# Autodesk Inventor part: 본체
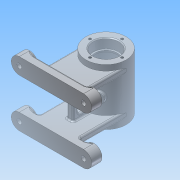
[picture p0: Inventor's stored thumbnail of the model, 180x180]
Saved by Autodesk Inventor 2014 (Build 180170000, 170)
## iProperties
Created: 2015-11
Part Number: 본체
Material: 알루미늄 6061
Document SubType Name: Modeling
Designer: net
Density: 2.71 g/cm^3
Appearance: 알루미늄 - 평지
Mass: 357.463 g
Surface Area: 461.435 cm^2
Volume: 131.905 cm^3
Author: net
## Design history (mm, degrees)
sketch "스케치1"
  geometry: C1 r 25 at (0, 0); 1 further point
  constraints: 1 centre point, 1 coincident
  dimensions: "d0" = 50 diameter of C1
extrude "돌출1" new body sketch "스케치1" stored distance "d1" = 70; taper "d2" = 0 deg
node "작업 평면1"
sketch "스케치2"
  geometry: L1 (-25, -35)-(25, -35) reference; L2 (25, 35)-(-25, 35) reference; L3 (40, -20)-(-40, -20); L4 (-40, -20)-(-40, -40); L5 (-40, -40)-(40, -40); L6 (40, -40)-(40, -20); L7 (40, 40)-(-40, 40); L8 (-40, 40)-(-40, 20); L9 (-40, 20)-(40, 20); L10 (40, 20)-(40, 40); 7 further points
  constraints: 16 end point, 6 midpoint, 6 vertical alignment, 4 parallel, 2 horizontal, 2 perpendicular, 8 other
  dimensions: "d4" = 40 distance from line of L5 point (0, 0); "d5" = 80 distance between parallel lines of L7 L5; "d6" = 20 distance of L7.end L8.end; "d7" = 20 distance of L3.end L4.end; "d8" = 80 distance of L4.end L5.end; "d9" = 80 distance of L7.start L7.end
  node "투영된 루프1"
extrude "돌출2" join sketch "스케치2" distance "d10" = 10; taper "d11" = 0 deg
extrude "돌출3" join sketch "스케치2" distance "d12" = 13; taper "d13" = 0 deg
node "작업 평면2"
sketch "스케치3"
  geometry: L1 (40, 40)-(-40, 40) reference; L2 (-40, 20)-(40, 20) reference; L3 (-40, -40)-(40, -40) reference; L4 (40, -20)-(-40, -20) reference; L5 (-25, 28)-(25, 28); L6 (25, 28)-(25, 20); L7 (25, 20)-(-25, 20); L8 (-25, 20)-(-25, 28); L9 (-25, -20)-(25, -20); L10 (25, -20)-(25, -28); L11 (25, -28)-(-25, -28); L12 (-25, -28)-(-25, -20); A1 r 10 centre (40, 30) between (40, 40) and (40, 20) reference; A2 r 10 centre (-40, 30) between (-40, 20) and (-40, 40) reference; A3 r 10 centre (-40, -30) between (-40, -40) and (-40, -20) reference; A4 r 10 centre (40, -30) between (40, -20) and (40, -40) reference; 5 further points
  constraints: 16 end point, 4 coincident, 4 midpoint, 4 parallel, 2 horizontal, 2 perpendicular
  dimensions: "d15" = 50 distance of L5.start L5.end; "d16" = 50 distance of L10.end L11.end; "d17" = 8 distance of L9.end L10.end; "d18" = 8 distance of L5.end L6.end
extrude "돌출4" join sketch "스케치3" stored distance "d19" = 13; taper "d20" = 0 deg
node "작업 평면3"
sketch "스케치4"
  geometry: L1 (-40, 20)-(40, 20) reference; L2 (40, -20)-(-40, -20) reference; L3 (4, 20)-(-4, 20); L4 (-4, 20)-(-4, -20); L5 (-4, -20)-(4, -20); L6 (4, -20)-(4, 20); 2 further points
  constraints: 8 end point, 2 parallel, 2 point on line, 1 horizontal, 1 midpoint, 1 perpendicular, 1 vertical alignment
  dimensions: "d22" = 8 distance between parallel lines of L4 L6
extrude "돌출5" join sketch "스케치4" stored distance "d23" = 13; taper "d24" = 0 deg
sketch "스케치5"
  geometry: L1 (-68, 40)-(-68, 20) reference; L2 (-24.678, 20)-(-24.678, -20) reference; L3 (-45, 20)-(-24.678, 20) reference; L4 (-45, 20)-(-45, -20) reference; L5 (-24.678, -20)-(-45, -20) reference; L6 (-31.5, 11.5)-(-31.5, -11.5); L7 (-38.5, 11.5)-(-38.5, -11.5); A1 r 3.5 centre (-35, 11.5) between (-31.5, 11.5) and (-38.5, 11.5); A2 r 3.5 centre (-35, -11.5) between (-38.5, -11.5) and (-31.5, -11.5); 2 further points
  constraints: 4 end point, 4 point on circle, 3 tangent, 2 centre point, 1 horizontal alignment, 1 midpoint, 1 parallel, 1 perpendicular
  dimensions: "d25" = 33 distance from line of A1.centre L1; "d26" = 7 diameter of A2; "d27" = 7 diameter of A1; "d28" = 23 distance of L7.start L7.end
extrude "돌출6" cut sketch "스케치5" stored distance "d29" = 13; taper "d30" = 0 deg
sketch "스케치6"
  geometry: L1 (25, 35)-(-25, 35) reference; L2 (25, -35)-(25, 35) reference; L3 (-25, -35)-(25, -35) reference; L4 (0, 62.563)-(0, -62.563); L5 (16, -35)-(16, -23); L6 (16, -23)-(14, -23); L7 (14, -23)-(14, -21); L8 (14, -21)-(21, -21); L9 (21, -21)-(21, 21); L10 (21, 21)-(14, 21); L11 (14, 21)-(14, 23); L12 (14, 23)-(16, 23); L13 (16, 23)-(16, 35); L14 (0, 35)-(16, 35); L15 (0, -35)-(16, -35); L16 (0, -35)-(0, 35); 3 further points
  constraints: 26 end point, 7 parallel, 4 midpoint, 4 point on line, 3 collinear, 3 perpendicular, 2 coincident, 1 horizontal alignment
  dimensions: "d31" = 32 diameter of L5 L4; "d32" = 28 diameter of L7 L4; "d33" = 32 diameter of L13 L4; "d34" = 28 diameter of L11 L4; "d35" = 42 diameter of L9 L4; "d36" = 12 distance of L5.start L5.end; "d37" = 12 distance of L12.end L13.end; "d38" = 42 distance of L8.end L9.end
revolve "회전1" sketch "스케치6" stored, may be unused: angle "d39" = 90 deg
node "작업 평면4"
sketch "스케치7"
  geometry: L1 (25, 35)-(-25, 35) reference; L2 (-25, -35)-(25, -35) reference; C1 r 5 at (0, 0); 1 further point
  constraints: 1 centre point, 1 coincident
  dimensions: "d41" = 10 diameter of C1
extrude "돌출7" join sketch "스케치7" stored distance "d42" = 13; taper "d43" = 0 deg
sketch "스케치8"
  geometry: L1 (0, 0)-(9.424, 0); L2 (0, 0)-(14, -24.249); L3 (0, 0)-(0, -8.439); C1 r 25 at (0, 0) reference; 1 further point
  constraints: 6 end point, 1 horizontal, 1 perpendicular
  dimensions: "d44" = 30 deg angle of L2 L3; "d45" = 28 distance of L1.start L2.end
node "작업 평면5"
sketch "스케치9"
  geometry: C1 r 6 at (0, 0); 1 further point
  constraints: 1 centre point, 1 coincident
  dimensions: "d46" = 12 diameter of C1
extrude "돌출8" join sketch "스케치9" stored distance "d47" = 13; taper "d48" = 0 deg
node "작업 평면6"
sketch "스케치10"
  geometry: 2 further points
  constraints: 2 coincident, 1 other
feature "엠보싱1" sketch "스케치10" dims "d4" = 40, "d5" = 80, "d6" = 20, "d7" = 20, "d8" = 80, "d9" = 80, "d49" = 0.5, "d50" = 0
fillet "모깎기1" dims "d51" = 0.3
chamfer "모따기1" distance "d52" = 1; stored, may be unused: second distance "d53" = 2, angle "d54" = 45 deg
fillet "모깎기2" dims "d55" = 3
fillet "모깎기3" dims "d56" = 2
fillet "모깎기4" dims "d57" = 2
fillet "모깎기5" dims "d58" = 2
fillet "모깎기6" dims "d59" = 2
fillet "모깎기7" dims "d60" = 2
fillet "모깎기8" dims "d61" = 2
fillet "모깎기9" dims "d62" = 2
hole "구멍1" diameter "d65" = 5.188; stored, may be unused: countersink angle "d69" = 90 deg, drill point angle "d71" = 118 deg; dims "d63" = 10, "d64" = 10, "d66" = 6, "d67" = 4, "d68" = 2, "d70" = 8
hole "구멍2" diameter "d74" = 5.188; stored, may be unused: countersink angle "d78" = 90 deg, drill point angle "d80" = 118 deg; dims "d72" = 10, "d73" = 10, "d75" = 6, "d76" = 4, "d77" = 2, "d79" = 8
sketch "스케치11"
  geometry: C1 r 25 at (0, 0) reference; 1 further point
  constraints: 1 vertical alignment
  dimensions: "d81" = 20 distance of C1.centre point (0, 20)
hole "구멍3" sketch "스케치11" at (0, 20) diameter "d82" = 3.242; stored, may be unused: countersink angle "d86" = 90 deg, drill point angle "d88" = 118 deg; dims "d83" = 8, "d84" = 4, "d85" = 2, "d87" = 10
sketch "스케치12"
  geometry: C1 r 25 at (0, 0) reference; 1 further point
  constraints: 1 vertical alignment
  dimensions: "d89" = 20 distance of C1.centre point (0, 20)
hole "구멍4" sketch "스케치12" at (0, 20) diameter "d90" = 3.242; stored, may be unused: countersink angle "d94" = 90 deg, drill point angle "d96" = 118 deg; dims "d91" = 8, "d92" = 4, "d93" = 2, "d95" = 10
hole "구멍5" diameter "d102" = 6; stored, may be unused: countersink angle "d106" = 90 deg, drill point angle "d108" = 118 deg; dims "d100" = 10, "d101" = 10, "d103" = 6, "d104" = 12, "d105" = 4, "d107" = 8
hole "구멍6" diameter "d111" = 6; stored, may be unused: countersink angle "d115" = 90 deg, drill point angle "d117" = 118 deg; dims "d109" = 10, "d110" = 10, "d112" = 6, "d113" = 12, "d114" = 4, "d116" = 8
hole "구멍7" diameter "d120" = 6; stored, may be unused: countersink angle "d124" = 90 deg, drill point angle "d126" = 118 deg; dims "d118" = 10, "d119" = 10, "d121" = 6, "d122" = 12, "d123" = 4, "d125" = 8
hole "구멍8" diameter "d129" = 6; stored, may be unused: countersink angle "d133" = 90 deg, drill point angle "d135" = 118 deg; dims "d127" = 10, "d128" = 10, "d130" = 6, "d131" = 12, "d132" = 4, "d134" = 8
fillet "모깎기10" dims "d136" = 0.3
chamfer "모따기2" distance "d137" = 1; stored, may be unused: second distance "d138" = 2, angle "d139" = 45 deg
node "솔리드1"
pattern_circular "원형 패턴1" dims angle "d98" = 360 deg
node "투영된 루프2"
node "투영된 루프3"
node "투영된 루프4"
other parameters: "d3" = -68, "d14" = -58, "d21" = -45, "d40" = 28
